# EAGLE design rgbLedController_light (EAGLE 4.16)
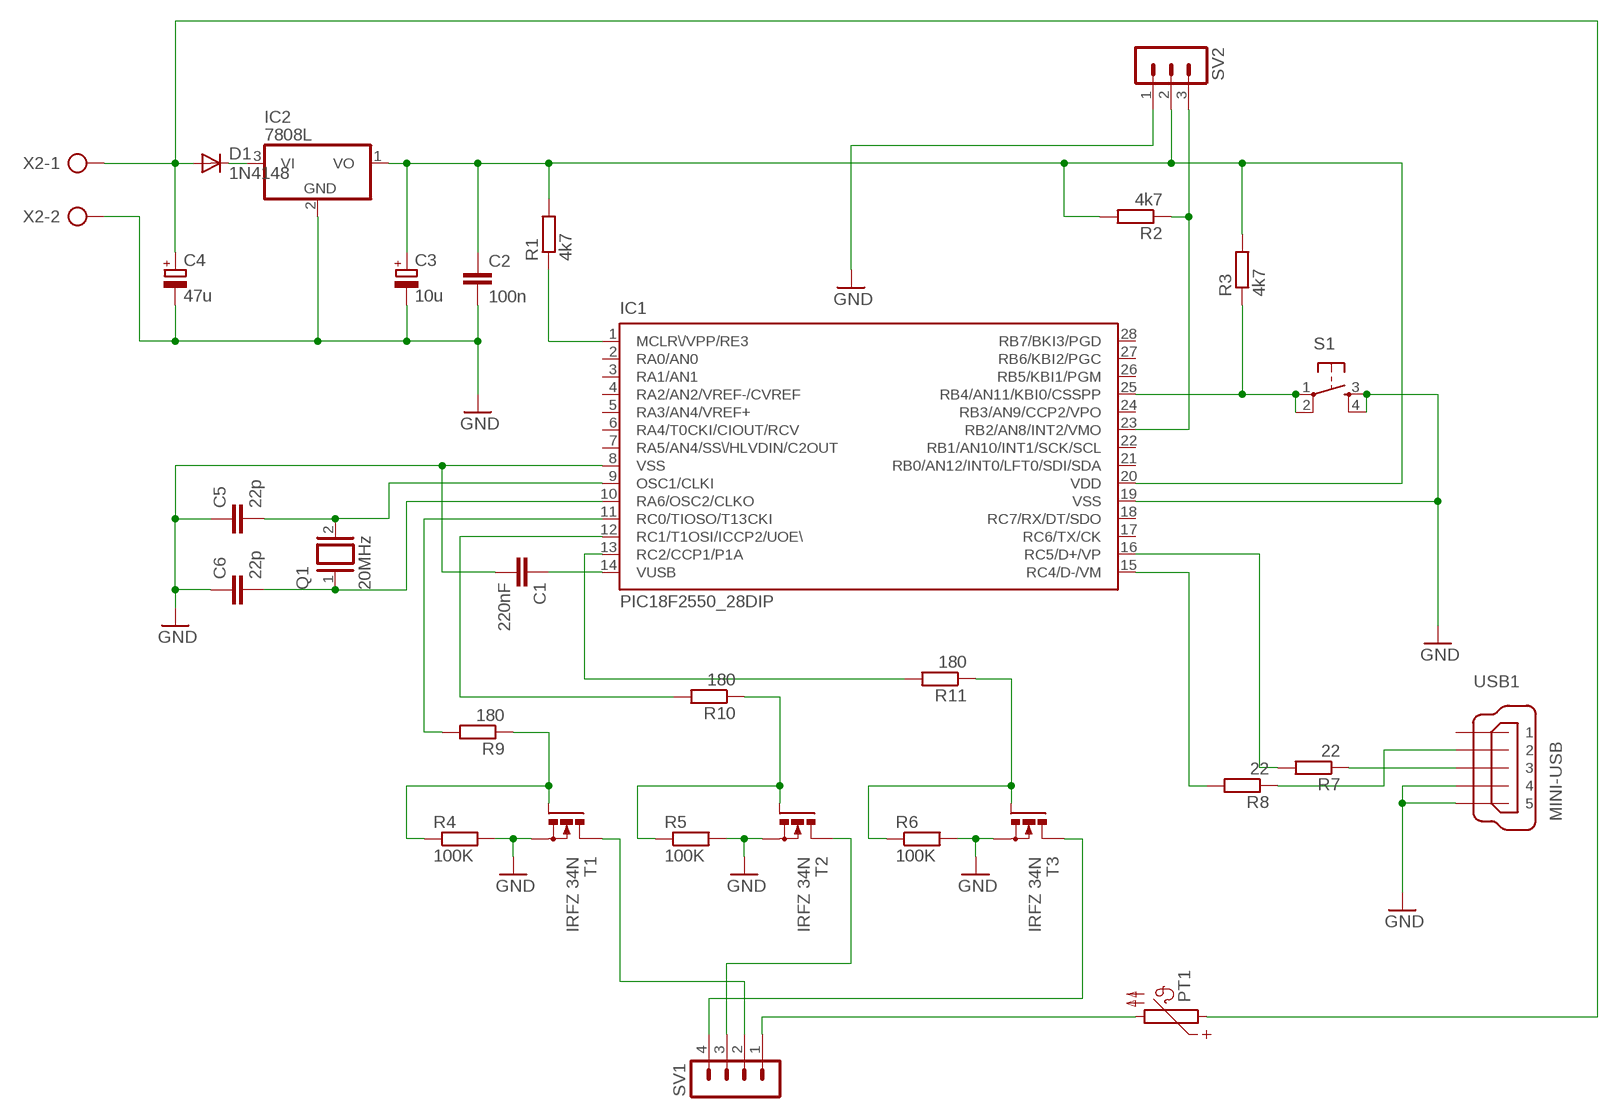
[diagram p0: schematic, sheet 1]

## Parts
C1  220nF  C-EU025-025X050  [C025-025X050]
C2  100n  C-EU025-025X050  [C025-025X050]
C3  10u  CPOL-EUE2,5-6E  [E2,5-6E]
C4  47u  CPOL-EUE2,5-6E  [E2,5-6E]
C5  22p  C-EU025-025X050  [C025-025X050]
C6  22p  C-EU025-025X050  [C025-025X050]
D1  1N4148  BAS15  [DO34-7]
IC1  PIC18F2550_28DIP  [DIL28-3]
IC2  7808L  [TO92]
PT1  PTC660  [P660]
Q1  20MHz  XTAL/S  [QS]
R1  4k7  R-EU_0207/7  [0207/7]
R2  4k7  R-EU_0207/7  [0207/7]
R3  4k7  R-EU_0207/7  [0207/7]
R4  100K  R-EU_0207/7  [0207/7]
R5  100K  R-EU_0207/7  [0207/7]
R6  100K  R-EU_0207/7  [0207/7]
R7  22  R-EU_0204/7  [0204/7]
R8  22  R-EU_0204/7  [0204/7]
R9  180  R-EU_0309/10  [0309/10]
R10  180  R-EU_0207/7  [0207/7]
R11  180  R-EU_0207/7  [0207/7]
S1  PRINTTASTER1  [PRINTTASTER1]
SV1  MA04-1  [MA04-1]
SV2  MA03-1  [MA03-1]
T1  IRFZ 34N  IRF512  [TO220BV]
T2  IRFZ 34N  IRF512  [TO220BV]
T3  IRFZ 34N  IRF512  [TO220BV]
USB1  MINI-USB  MINI-USB_SHIELD5P2-32005-601  [32005-601]
X2  AK500/2  [AK500/2]

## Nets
GND: C1.2 C2.2 C3.- C4.- C5.1 C6.1 IC1.8(VSS) IC1.19(VSS) IC2.2(GND) R4.2 R5.2 R6.2 S1.3(S) S1.4(S1) SV2.1 T1.S T2.S T3.S USB1.4 USB1.5 X2.2
N$1: IC1.23(RB2/AN8/INT2/VMO) R2.1 SV2.3
N$2: C4.+ D1.A PT1.1 X2.1
N$3: R4.1 R9.1 T1.G
N$4: R5.1 R10.1 T2.G
N$5: C6.2 IC1.10(RA6/OSC2/CLKO) Q1.1
N$6: R6.1 R11.1 T3.G
N$7: PT1.2 SV1.1
N$8: D1.C IC2.3(VI)
N$9: C5.2 IC1.9(OSC1/CLKI) Q1.2
N$11: IC1.1(MCLR\/VPP/RE3) R1.1
N$12: IC1.16(RC5/D+/VP) R7.2
N$13: IC1.15(RC4/D-/VM) R8.2
N$14: R7.1 USB1.3
N$15: R8.1 USB1.2
N$16: IC1.25(RB4/AN11/KBI0/CSSPP) R3.1 S1.1(P) S1.2(P1)
N$18: IC1.11(RC0/TIOSO/T13CKI) R9.2
N$19: C1.1 IC1.14(VUSB)
N$20: IC1.12(RC1/T1OSI/ICCP2/UOE\) R10.2
N$21: IC1.13(RC2/CCP1/P1A) R11.2
N$22: SV1.2 T1.D
N$23: SV1.3 T2.D
N$24: SV1.4 T3.D
VDD: C2.1 C3.+ IC1.20(VDD) IC2.1(VO) R1.2 R2.2 R3.2 SV2.2
Unconnected: IC1.2(RA0/AN0) IC1.3(RA1/AN1) IC1.4(RA2/AN2/VREF-/CVREF) IC1.5(RA3/AN4/VREF+) IC1.6(RA4/T0CKI/CIOUT/RCV) IC1.7(RA5/AN4/SS\/HLVDIN/C2OUT) IC1.17(RC6/TX/CK) IC1.18(RC7/RX/DT/SDO) IC1.21(RB0/AN12/INT0/LFT0/SDI/SDA) IC1.22(RB1/AN10/INT1/SCK/SCL) IC1.24(RB3/AN9/CCP2/VPO) IC1.26(RB5/KBI1/PGM) IC1.27(RB6/KBI2/PGC) IC1.28(RB7/BKI3/PGD) USB1.1 USB1.M1(S1) USB1.M2(S2)

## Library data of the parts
C1 C2 C5 C6 = rcl:C-EU: CAPACITOR, European symbol
C3 C4 = rcl:CPOL-EU: POLARIZED CAPACITOR, European symbol
D1 = diode:BAS15: DIODE
IC1 = microchip:PIC18F2*_28: USB Microcontrollers with nanoWatt Technology High-Performance, Enhanced Flash, 28/40/44-Pin, Source: http://ww1.microchip.com/downloads/en/devicedoc/39632c.pdf
IC2 = linear:78*: Positive VOLTAGE REGULATOR Source: http://cache.national.com/ds/LM/LM78L05.pdf http://www.fairchildsemi.com/ds/LM/LM7805.pdf
PT1 = ptc-ntc:PTC660: PHILIPS PTC
Q1 = special:XTAL/S: CRYSTAL
R1-R11 = rcl:R-EU_: RESISTOR, European symbol
S1 = Taster:PRINTTASTER1
SV1 = con-lstb:MA04-1: PIN HEADER
SV2 = con-lstb:MA03-1: PIN HEADER
T1-T3 = transistor-power:IRF512: N-CHANNEL MOS FET
USB1 = con-cypressindustries:MINI-USB_SHIELD5P2-: MINI USB-B R/A DIP 5pol. Source: www.cypressindustries.com
X2 = con-ptr500:AK500/2: CONNECTOR

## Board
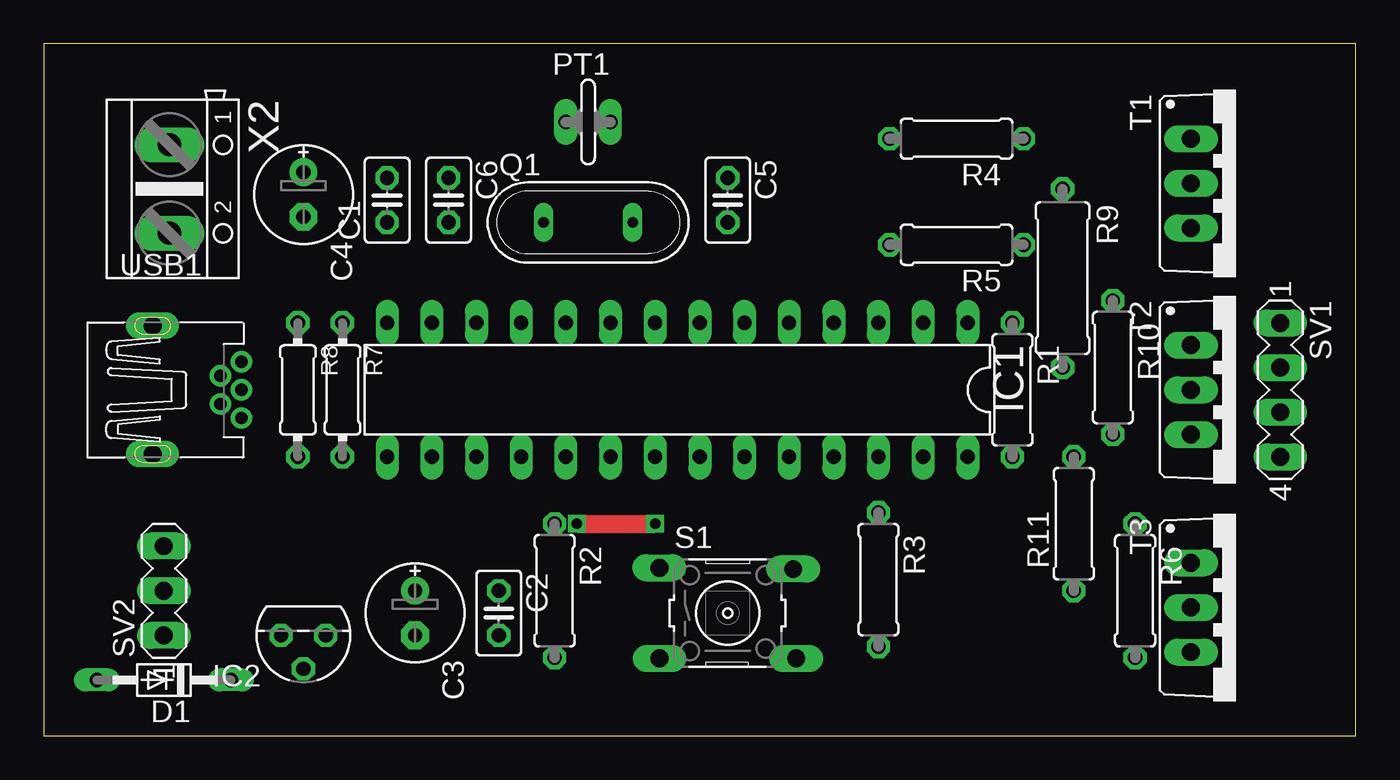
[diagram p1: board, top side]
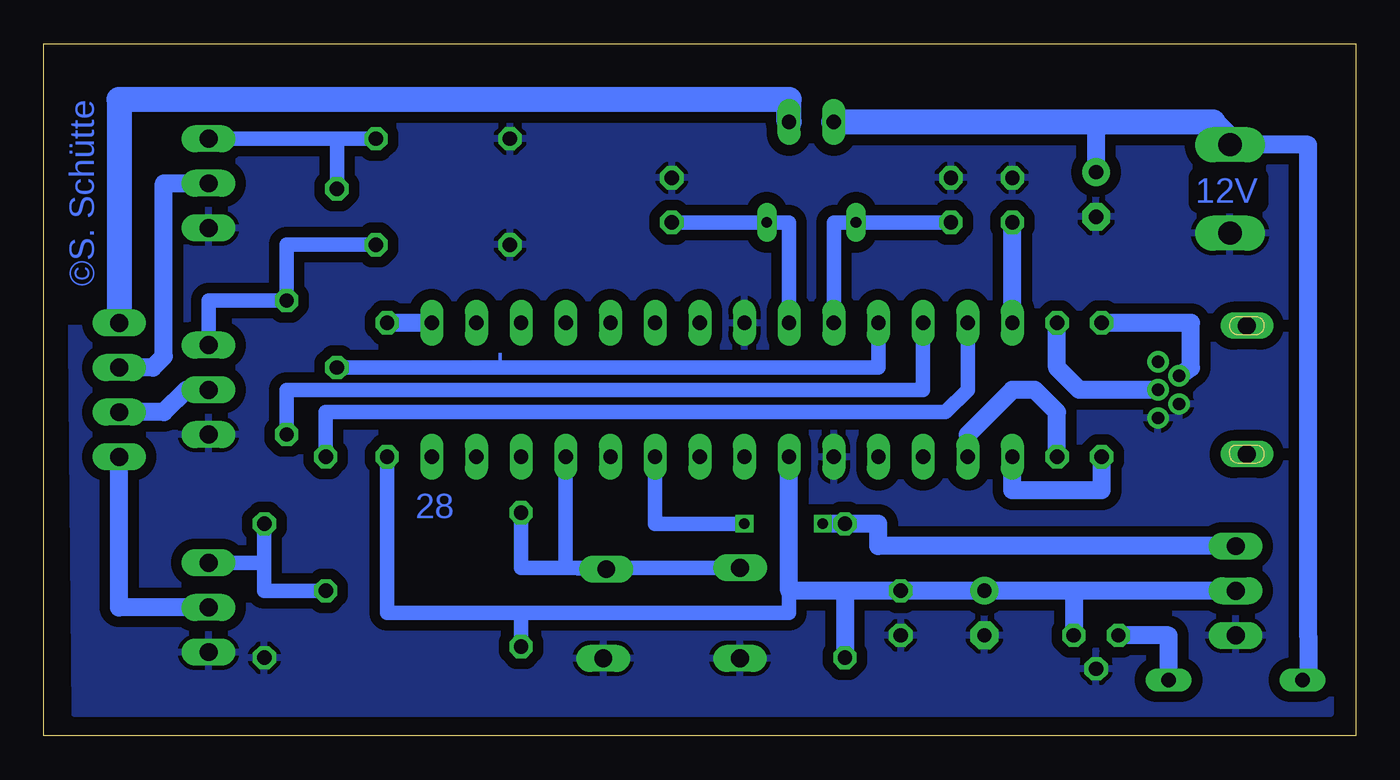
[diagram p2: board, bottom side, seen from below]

Size 74.6 x 39.36 mm. Coordinates in mm from the lower left corner, seen from the top.
Outline: 0,0 74.6,0 74.6,39.36 0,39.36 0,0
Copper layers (1*16): Top 0.035mm / dielectric 1.5mm / Bottom 0.035mm
Design rules "default": minimum track width 10mil, minimum drill 24mil, track to track 8mil, track to pad 8mil, pad to pad 8mil, via to via 8mil, smd to smd 8mil, copper to edge 40mil, drill to drill 8mil, minimum pad ring 10mil, minimum via ring 8mil, stop-mask expansion 4mil, vias tented up to drill 0mil, thermal gap 10mil

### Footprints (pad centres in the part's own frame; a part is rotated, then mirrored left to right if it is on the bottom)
C025-025X050 = drill 0.813 octagon: 1 -1.27,0; 2 1.27,0
E2,5-6E = drill 0.813 pad 1.575 round: + -1.27,0 | drill 0.813 pad 1.575 octagon: - 1.27,0
DO34-7 = drill 0.813 long: A 3.81,0; C -3.81,0
DIL28-3 = drill 0.813 long: 1 -16.51,-3.81; 2 -13.97,-3.81; 3 -11.43,-3.81; 4 -8.89,-3.81; 5 -6.35,-3.81; 6 -3.81,-3.81; 7 -1.27,-3.81; 8 1.27,-3.81; 9 3.81,-3.81; 10 6.35,-3.81; 11 8.89,-3.81; 12 11.43,-3.81; 13 13.97,-3.81; 14 16.51,-3.81; 15 16.51,3.81; 16 13.97,3.81; 17 11.43,3.81; 18 8.89,3.81; 19 6.35,3.81; 20 3.81,3.81; 21 1.27,3.81; 22 -1.27,3.81; 23 -3.81,3.81; 24 -6.35,3.81; 25 -8.89,3.81; 26 -11.43,3.81; 27 -13.97,3.81; 28 -16.51,3.81
TO92 = drill 0.813 octagon: 1 -1.27,0; 2 0,1.905; 3 1.27,0
P660 = drill 0.813 long: 1 -1.27,0; 2 1.27,0
QS = drill 0.61 long: 1 -2.54,0; 2 2.54,0
0207/7 = drill 0.813 octagon: 1 -3.81,0; 2 3.81,0
0204/7 = drill 0.813 octagon: 1 -3.81,0; 2 3.81,0
0309/10 = drill 0.813 octagon: 1 -5.08,0; 2 5.08,0
PRINTTASTER1 = drill 1.016 long: 1 -3.885,2.578; 2 3.731,2.502; 3 -3.881,-2.578; 4 3.897,-2.578
MA04-1 = drill 1.016 long: 1 -3.81,0; 2 -1.27,0; 3 1.27,0; 4 3.81,0
MA03-1 = drill 1.016 long: 1 -2.54,0; 2 0,0; 3 2.54,0
TO220BV = drill 1.016 long: D 0,-2.54; G -2.54,-2.54; S 2.54,-2.54
32005-601 = drill 0.7 pad 1.016 round: 1 2.825,1.6; 2 1.625,0.8; 3 2.825,0; 4 1.625,-0.8; 5 2.825,-1.6 | drill 1 pad 1.422 long: M1 -2.225,3.65; M2 -2.225,-3.65
AK500/2 = drill 1.321 long: 1 -2.515,0; 2 2.515,0

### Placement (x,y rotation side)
C1  19.52,30.48 90 top
C2  25.87,6.98 270 top
C3  21.11,6.98 270 top
C4  14.76,30.79 270 top
C5  38.89,30.48 270 top
C6  23.01,30.48 270 top
D1  6.82,3.17 180 top
IC1  36.03,19.68 180 top
IC2  14.76,5.71 180 top
PT1  30.95,34.92 0 top
Q1  30.95,29.2 0 top
R1  55.08,19.68 270 top
R2  29.04,8.25 270 top
R3  47.46,8.88 270 top
R4  51.91,33.97 180 top
R5  51.91,27.94 180 top
R6  62.06,8.25 270 top
R7  16.98,19.68 270 top
R8  14.44,19.68 270 top
R9  57.94,26.03 270 top
R10  60.8,20.95 270 top
R11  58.57,12.06 90 top
S1  38.89,6.98 0 top
SV1  70.32,19.68 270 top
SV2  6.82,8.25 90 top
T1  67.78,31.43 270 top
T2  67.78,19.68 270 top
T3  67.78,7.3 270 top
USB1  8.41,19.68 0 top
X2  7.14,31.11 270 top

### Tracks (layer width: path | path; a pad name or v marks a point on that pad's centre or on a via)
GND
  pour Bottom (isolate 0.61): 72.86,1.27 1.42,1.27 1.42,37.46 73.18,37.46
N$1  (via drill 0.6)
  Top 1.016: v30.31,12.06 v34.76,12.06
  Bottom 0.813: IC1.23 39.84,12.06 v34.76,12.06
  Bottom 1.016: v30.31,12.06 R2.1 27.14,12.06 27.14,10.79 SV2.3
N$2
  Bottom 0.406: X2.1 8.09,33.62 | 2.69,2.85 2.69,3.17 D1.A
  Bottom 1.016: 6.82,33.62 2.69,33.62 2.69,5.71 2.69,3.17 | 14.76,34.92 C4.+
  Bottom 1.27: X2.1 6.82,33.62 8.09,34.92
  Bottom 1.422: 8.09,34.92 14.76,34.92 PT1.1
N$3
  Bottom 0.813: R9.1 57.94,33.97 | 57.94,33.97 R4.1 | 57.94,33.97 T1.G
N$4
  Bottom 0.813: T2.G 65.24,24.76 R10.1 60.8,27.94 R5.1
N$5
  Bottom 0.813: IC1.10 29.68,29.2 Q1.1 C6.2
N$6
  Bottom 0.813: R11.1 62.06,8.25 62.06,9.84 | 62.06,9.84 T3.G | 62.06,9.84 R6.1
N$7
  Bottom 1.422: SV1.1 70.32,36.19 32.22,36.19 PT1.2
N$8
  Bottom 1.016: D1.C 10.63,5.71 IC2.3
N$9
  Bottom 0.406: Q1.2 33.49,28.57
  Bottom 0.813: C5.2 Q1.2 32.22,29.2 IC1.9
N$11
  Bottom 1.016: IC1.1 R1.1
N$12
  Bottom 1.016: IC1.16 22.06,17.14 19.52,19.68 18.25,19.68 16.98,18.41 R7.2
N$13
  Bottom 1.016: IC1.15 19.52,13.97 14.44,13.97 R8.2
N$14
  Bottom 1.016: USB1.3 15.71,19.68 16.98,20.95 R7.1
N$15
  Bottom 1.016: R8.1 9.36,23.49 9.36,20.95 9.4,20.91 USB1.2
N$16
  Bottom 0.813: 44.92,9.56 IC1.25 | S1.2 43.65,9.48 44.92,9.56 | S1.1 44.92,9.56 | 44.92,9.56 47.46,9.56 R3.1
N$18
  Bottom 0.813: IC1.11 27.14,20.95 R9.2
N$19
  Bottom 1.016: IC1.14 C1.1
N$20
  Bottom 0.813: IC1.12 24.6,19.68 60.8,19.68 R10.2
N$21
  Bottom 0.813: IC1.13 22.06,19.68 23.33,18.41 58.57,18.41 R11.2
N$22
  Bottom 1.016: T1.D 67.78,31.43 67.78,21.59 68.41,20.95 SV1.2
N$23
  Bottom 1.016: T2.D 66.51,19.68 67.78,18.41 SV1.3
N$24
  Bottom 1.016: T3.D 70.32,7.3 SV1.4
VDD
  Bottom 0.813: R1.2 55.08,6.98 47.46,6.98 | 47.46,6.98 R3.2 | 32.22,8.25 32.22,6.98 47.46,6.98
  Bottom 1.016: IC1.20 32.22,8.25 29.04,8.25 | SV2.2 16.03,8.25 | 29.04,8.25 R2.2 | 16.03,8.25 IC2.1 | 16.03,8.25 C3.+ C2.1 29.04,8.25

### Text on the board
Bottom: ©S. Schütte | 12V | 1 | 28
